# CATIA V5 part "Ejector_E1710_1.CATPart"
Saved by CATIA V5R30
Part number: Vyhazovac_4x160
Nomenclature: E1710/4x160
Description: MEUSBURGER
Property "Material": "1.221"
Publications: "__DrillHole", "Base"
Bounding box of the stored display mesh (mm): x -3.996 to 3.996, y -3.999 to 3.999, z 0 to 152
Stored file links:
  E:\Bakalarka\Model\Forma_v7\Ejector_E1710_1.CATPart
  E:\dev\MoldDesign\intel_a\startup\components\MoldCatalog\Ejector\Meusburger\Ejector_E1710\TableE1710.txt
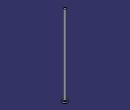
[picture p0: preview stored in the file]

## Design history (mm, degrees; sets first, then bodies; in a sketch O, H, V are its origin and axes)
Parameters
  Ref = "E1710/4x160" {design table}
  D1 = 4 mm {design table}
  D3 = 8 mm {design table}
  L = 160 mm {design table}
  L3 = 3 mm {design table}
  R = 0.3 mm {design table}
  k_d3 = 9 mm {design table}
  k_d1 = 4.2 mm {design table}
  k_F = 0.3 mm {design table}
  kl = 17 mm {design table}
  Mat = "1.221" {design table}
  HeatTreat = "ISO6751" {design table}
  Offset_Parting = 10 mm
  Anti_Rotation = "Normal"
  Anti_Rotation_D = 2.3 mm
  Anti_Rotation_D_Icut = 2.3 mm
  Add_Length_L = 0.8377 mm
  Add_Length_D3 = 0 mm
  SupplierRef = "Meusburger 2017"
  BmpRef = "F_MldEjectorD1"
  DrillHole_Length = 225 mm
  ValidationTest = false
  Anti_Rotation_D_min = 2.3 mm {= OffSet_D1 /2}
  Anti_Rotation_D_max = 3.925 mm {= D3/2-0.075mm}
  Anti_Rotation_D_ref = 2.3 mm {= Anti_Rotation_D}
  Anti_Rotation_D_Icut_ref = 2.3 mm {= Anti_Rotation_D_Icut}
  Anti_Rotation_Ref_Icut = 2.3246 mm
  Offset_L = 20 mm
  D = 4 mm {= D1}
  OffSet_D1 = 4.6 mm {= D1+2*R}
  OffSet_D3 = 9 mm {= D3+1mm}
  XG_Split = -154.5 mm
  YG_Split = 22.5 mm
  ZG_Split = -198 mm
  DirX_Split = 0 mm
  DirY_Split = 0 mm
  DirZ_Split = 1 mm
Set1 "BaseBody"
  Point1 "Base": (0, 0, 0)
  Plane1: type Offset, RefPlane xy-plane, Offset 225 {= DrillHole_Length}, reversed
  Sketch1 "Sketch.2" on xy-plane, origin (0, 0, 0), H (1, 0, 0), V (0, 1, 0)
    point P1 (-0.46, 1.1623)
    point P2 (0.46, 1.1623)
    construction line L1 (-0.46, 1.1623) -> (0.46, 1.1623)
    point P3 (0.46, -1.1623)
    line L2 (0.46, -1.1623) -> (0.46, 1.1623)
    point P4 (-0.46, -1.1623)
    construction line L3 (0.46, -1.1623) -> (-0.46, -1.1623)
    line L4 (-0.46, 1.1623) -> (-0.46, -1.1623)
    point P5 (-0.21, 1.1623)
    arc A1 centre (-0.21, 1.1623) radius 0.25 from (-0.21, 1.4123) to (-0.46, 1.1623) ccw
    point P7 (0.21, 1.1623)
    point P8 (0.21, 1.4123)
    arc A2 centre (0.21, 1.1623) radius 0.25 from (0.46, 1.1623) to (0.21, 1.4123) ccw
    line L5 (-0.21, 1.4123) -> (0.21, 1.4123)
    point P9 (-0.46, -1.1623)
    arc A3 centre (-0.21, -1.1623) radius 0.25 from (-0.46, -1.1623) to (-0.21, -1.4123) ccw
    point P11 (0.21, -1.4123)
    line L6 (-0.21, -1.4123) -> (0.21, -1.4123)
    point P12 (0.46, -1.1623)
    arc A4 centre (0.21, -1.1623) radius 0.25 from (0.21, -1.4123) to (0.46, -1.1623) ccw
    point P14 (-0.46, 1.1623)
    point P15 (-0.46, -1.1623)
    point P16 (0.46, 1.1623)
    point P17 (0.46, -1.1623)
    reference projected circle E1 centre (0, 0) radius 1.25 from edge [face of Shaft1 from Sketch2.L3 | face of Shaft1 from Sketch2.L4]
    reference projected circle E2 centre (0, 0) radius 1.25 from edge [face of Shaft1 from Sketch2.L3 | face of Shaft1 from Sketch2.L4]
    reference projected circle E3 centre (0, 0) radius 1.25 from edge [face of Shaft1 from Sketch2.L3 | face of Shaft1 from Sketch2.L4]
    reference projected circle E4 centre (0, 0) radius 1.25 from edge [face of Shaft1 from Sketch2.L3 | face of Shaft1 from Sketch2.L4]
    point P18 (-0.46, -1.1623)
    point P19 (-0.21, -1.4123)
    point P20 (0.21, -1.4123)
    point P21 (0.46, -1.1623)
    point P22 (-0.21, -1.4123)
    point P23 (0.21, -1.4123)
    distance P14 P15 = 2.3246 (reference)
    distance P16 P17 = 2.3246 (reference)
    distance L1 P14 = 0 (reference)
    radius A1 = 2
    distance L4 V = 2.31
    distance L2 V = 3.935
    distance L5 L6 = 8
    horizontal: L1 H, L3 H, L5 H
    vertical: L2 V, L4 V
    coincidence: P5 L1, P7 L1, P3 P12, P14 L4, P15 L4, P16 L2, P17 L2, P14 E1, P15 E2, P16 E3, P17 E4, P3 P21, P4 P18, P20 P23, P19 P22
    tangency: A1 L4, A2 L2, A2 L5, A1 L5
    symmetry: P1 P9 H, A1 A3 H, P8 P11 H, L5 L6 H, P2 P12 H, A2 A4 H
  DatumSurface1
Body1 "PartBody" (main body)
  Sketch2 "Sketch.1" on zx-plane, origin (0, 0, 0), H (-1, 0, 0), V (0, 0, 1)
    point P1 (0, 160)
    line L1 (2, 160) -> (0, 160)
    line L2 (2, 3) -> (2, 160)
    line L3 (4, 3) -> (2, 3)
    line L4 (4, 0) -> (4, 3)
    point P5 (0, 0)
    line L5 (0, 0) -> (4, 0)
    point P6 (0, 160)
    axis line L6 (0, 160) -> (0, 0)
    point P7 (0, 0)
    point P8 (2, 3)
    point P9 (2, 3)
    line L7 (0, 160) -> (0, 0)
    distance L5 L3 = 3 {= L3}
    distance L5 L1 = 160 {= L}
    distance L2 L6 = 2 {= D1 /2}
    distance L4 L6 = 4 {= D3 /2}
    coincidence: L6 P5, P1 L6, L5 H, L6 V, P7 O, P6 P1, P8 P9
    vertical: L2 V, L7 V
    horizontal: L1 H
  Shaft1 "Shaft.1": profile Sketch2, axis Sketch2.L6, angle 360
  Pocket1 "Pocket.1": profile Sketch1, direction (0, 0, 1), length 4, outer side, deactivated
  Pocket2 "Pocket.2": profile Sketch1, direction (0, 0, 1), length 4, outer side, deactivated
  Fillet1: radius 0.3 {= R}, on edge [face of Shaft1 from Sketch2.L2 | face of Shaft1 from Sketch2.L3]
  Pocket3: profile face of Shaft1 from Sketch2.L1, direction along face of Shaft1 from Sketch2.L1 reversed, up to face of DatumSurface1
Body2 "__DrillHole"
  Sketch3 "Sketch.3" on face of Shaft1, origin (0, 0, 0), H (1, 0, 0), V (0, -1, 0)
    point P1 (0, 0)
    reference projected point E1 (0, 0) from Point1
    coincidence: E1 P1
  Hole1 "Hole.1": placed by Sketch3, at (0, 0, 0) direction (0, 0, 1), diameter 4.6 {= OffSet_D1}, depth 140 {= L-Offset_L}
  Sketch4 "Sketch.4" on face of Shaft1, origin (0, 0, 0), H (1, 0, 0), V (0, -1, 0)
    point P1 (0, 0)
    reference projected point E1 (0, 0) from Point1
    coincidence: E1 P1
  Hole2 "Hole.2": placed by Sketch4, at (0, 0, 0) direction (0, 0, 1), diameter 4 {= D1}, depth 160 {= L}
  Sketch5 "Sketch.5" on face of Shaft1 from Sketch2.L3, origin (0, 0, 3), H (1, 0, 0), V (0, 1, 0)
    point P1 (0, 0)
    reference projected point E1 (0, 0) from Point1
    coincidence: E1 P1
  Hole3 "Hole.3": placed by Sketch5, at (0, 0, 3) direction (0, 0, -1), diameter 9 {= OffSet_D3}, depth 228 {= L3 +DrillHole_Length}
  Chamfer1: length 0.3 {= k_F}, angle 45, on edge [face of Hole1 | face of Hole3]
  Body3 "__Body.1"
    Pocket4 "Pocket.3": profile Sketch1, direction (0, 0, -1), length 225, opposite side length 3, deactivated
  Assemble1: tool Body3
  Chamfer2: length 0.3 {= k_F}, angle 45, on edge [start face of Pocket4 | face of Hole1], deactivated
  Body4 "__Body.2"
    Pocket5 "Pocket.4": profile Sketch1, direction (0, 0, -1), length 225, opposite side length 3, deactivated
  Assemble2: tool Body4
  Chamfer3: length 0.3 {= k_F}, angle 45, on edge [start face of Pocket5 | face of Hole1], deactivated
Relations
  design table "TableE1710", configuration 187, drives Ref, D1, D3, L, L3, R, k_d3, k_d1, k_F, kl, Mat, HeatTreat
  Offset_L = 20mm (deactivated)
  rule "Cut_Head_rule":
    let sketch_cut (length)
    let PartBody_Pocket_Sketch (Boolean)
    let I_PartBody_Pocket (Boolean)
    let D_PartBody_Pocket (Boolean)
    let N_DrillHole_Hole (Boolean)
    let N_DrillHole_Hole_Sketch (Boolean)
    let I_DrillHole_Pocket (Boolean)
    let D_DrillHole_Pocket (Boolean)
    /* --------------------------------------------------------------------------------------*/
    if Anti_Rotation =="Normal"
    {
    	sketch_cut=Anti_Rotation_D_max
    	PartBody_Pocket_Sketch = false
    	I_PartBody_Pocket = false
    	D_PartBody_Pocket = false
    	N_DrillHole_Hole = true
    	N_DrillHole_Hole_Sketch = true
    	I_DrillHole_Pocket = false
    	D_DrillHole_Pocket = false
    	Chamfer1.Activity= true
    	Chamfer2.Activity= false
    	Chamfer3.Activity= false
    }
    if Anti_Rotation == "I_Cut"
    {
    	sketch_cut=Anti_Rotation_D_Icut_ref
    	PartBody_Pocket_Sketch = true
    	I_PartBody_Pocket = true
    	D_PartBody_Pocket = false
    	N_DrillHole_Hole = false
    	N_DrillHole_Hole_Sketch = false
    	I_DrillHole_Pocket = true
    	D_DrillHole_Pocket = false
    	Chamfer1.Activity= false
    	Chamfer2.Activity= true
    	Chamfer3.Activity= false
    }
    if Anti_Rotation =="D_Cut"
    {
    	sketch_cut=Anti_Rotation_D_max
    	PartBody_Pocket_Sketch = true
    	I_PartBody_Pocket = false
    	D_PartBody_Pocket = true
    	N_DrillHole_Hole = false
    	N_DrillHole_Hole_Sketch = false
    	I_DrillHole_Pocket = false
    	D_DrillHole_Pocket = true
    	Chamfer1.Activity= false
    	Chamfer2.Activity= false
    	Chamfer3.Activity= true
    }
    /* --------------------------------------------------------------------------------------*/
    Sketch1.distance(L2 V) = sketch_cut+0.01mm
    Sketch1.distance(L4 V) =Anti_Rotation_D_ref+0.01mm
    Sketch1.radius(A1) =D/2
    Pocket4.FirstLimit.Depth = DrillHole_Length
    Pocket5.FirstLimit.Depth = DrillHole_Length
    Pocket1.FirstLimit.Depth = L3+1mm
    Pocket2.FirstLimit.Depth = L3+1mm
    Pocket4.SecondLimit.Depth = L3
    Pocket5.SecondLimit.Depth =L3
    Pocket1.Activity = I_PartBody_Pocket
    Pocket2.Activity = D_PartBody_Pocket
    Sketch1.Activity =PartBody_Pocket_Sketch
    Hole3.Activity= N_DrillHole_Hole
    Sketch5.Activity = N_DrillHole_Hole_Sketch
    Pocket4.Activity = I_DrillHole_Pocket
    Pocket5.Activity  = D_DrillHole_Pocket
  rule "Anti_Rotation_Icut_constrain":
    let Ref1(length)
    let Ref2(length)
    let Ref3(length)
    let Diam1(length)
    let Diam2(length)
    let Add_Length_Lmin (length)
    Ref1=Sketch1.distance(P14 P15)
    Ref2=Sketch1.distance(P16 P17)
    Diam1=D
    Diam2=D3
    /* --------------------------------------------------------------------*/
    if Ref1 >Ref2
    	Anti_Rotation_Ref_Icut = Ref1
    else
    	Anti_Rotation_Ref_Icut  =Ref2
    Add_Length_D3 .InferiorRange=Anti_Rotation_Ref_Icut /2+Diam1/2 -Diam2/2
    if Add_Length_D3 .InferiorRange<0mm
    	Add_Length_D3 .InferiorRange=0mm
    if ValidationTest == "true"
    	Ref3   = 2*Add_Length_L +Anti_Rotation_Ref_Icut  +2*Diam1/2
    else
    	Ref3  =Diam2+2*Add_Length_D3
    if Ref3 <Diam2
    {
    	Ref3 =Diam2
    }
    /* --------------------------------------------------------------------*/
    Sketch1.distance(L5 L6) = Ref3
    Add_Length_L .InferiorRange=Diam2/2-Anti_Rotation_Ref_Icut/2-Diam1/2
    Add_Length_Lmin=Diam2/2-Anti_Rotation_Ref_Icut/2-Diam1/2
    if Add_Length_Lmin<0mm
    	Add_Length_L .InferiorRange=0mm
    else
    	Add_Length_L .InferiorRange=Add_Length_Lmin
